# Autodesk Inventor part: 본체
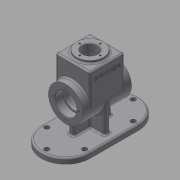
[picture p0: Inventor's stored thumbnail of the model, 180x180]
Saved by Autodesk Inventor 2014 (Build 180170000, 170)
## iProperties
Created: 2019-01
Part Number: 본체
Material: 일반
Document SubType Name: Modeling
Designer: mduedu
Density: 1 g/cm^3
Appearance: 기본값
Mass: 390.301 g
Surface Area: 916.19 cm^2
Volume: 390.301 cm^3
Author: mduedu
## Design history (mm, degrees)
sketch "스케치1"
  geometry: C1 r 32 at (0, 0); 1 further point
  constraints: 1 centre point, 1 coincident
  dimensions: "d0" = 64 diameter of C1
extrude "돌출1" new body sketch "스케치1" stored distance "d1" = 90; taper "d2" = 0 deg
sketch "스케치2"
  geometry: L1 (0, 32)-(60, 32); L2 (60, 32)-(60, -32); L3 (60, -32)-(0, -32); L4 (0, -32)-(0, 32); C1 r 32 at (0, 0) reference; 2 further points
  constraints: 8 end point, 2 parallel, 1 coincident, 1 horizontal, 1 midpoint, 1 perpendicular, 1 tangent
  dimensions: "d5" = 60 distance between parallel lines of L4 L2
extrude "돌출2" join sketch "스케치2" stored distance "d7" = 64; taper "d8" = 0 deg
sketch "스케치3"
  geometry: C1 r 25 at (32, 32); 1 further point
  constraints: 1 centre point, 1 coincident
  dimensions: "d9" = 50 diameter of C1
extrude "돌출3" join sketch "스케치3" distance "d10" = 5; taper "d11" = 0 deg
sketch "스케치4"
  geometry: L1 (50, 25)-(0, 25); L2 (0, 25)-(0, -25); L3 (0, -25)-(50, -25); L4 (50, -25)-(50, 25); L5 (65, -25)-(65, 25) reference; A1 r 25 centre (0, 0) between (0, 25) and (0, -25); A2 r 25 centre (0, 0) between (0, -25) and (0, 25); 2 further points
  constraints: 8 end point, 4 point on circle, 2 centre point, 2 coincident, 2 parallel, 1 horizontal, 1 midpoint, 1 perpendicular, 1 tangent
  dimensions: "d12" = 50 diameter of A1; "d13" = 15 distance between parallel lines of L4 L5
extrude "돌출4" cut sketch "스케치4" stored distance "d14" = 48; taper "d15" = 0 deg
sketch "스케치5"
  geometry: C1 r 20 at (0, 0); 1 further point
  constraints: 1 centre point, 1 coincident
  dimensions: "d16" = 40 diameter of C1
extrude "돌출5" cut sketch "스케치5" distance "d17" = 15; taper "d18" = 0 deg
sketch "스케치6"
  geometry: C1 r 17 at (0, 0); 1 further point
  constraints: 1 centre point, 1 coincident
  dimensions: "d19" = 34 diameter of C1
extrude "돌출6" cut sketch "스케치6" stored distance "d20" = 15; taper "d21" = 0 deg
fillet "모깎기1" dims "d22" = 0.3
fillet "모깎기2" dims "d23" = 3
fillet "모깎기3" dims "d24" = 3
fillet "모깎기4" dims "d25" = 3
fillet "모깎기5" dims "d26" = 3
fillet "모깎기6" dims "d27" = 3
sketch "스케치7"
  geometry: C1 r 14 at (0, 0); 1 further point
  constraints: 1 centre point, 1 coincident
  dimensions: "d28" = 28 diameter of C1
extrude "돌출7" cut sketch "스케치7" stored distance "d29" = 15; taper "d30" = 0 deg
chamfer "모따기1" distance "d31" = 1; stored, may be unused: second distance "d32" = 2, angle "d33" = 45 deg
chamfer "모따기2" distance "d34" = 1; stored, may be unused: second distance "d35" = 2, angle "d36" = 45 deg
node "작업 평면1"
sketch "스케치8"
  geometry: L1 (45, 45)-(-45, 45); L2 (-45, 45)-(-45, -45); L3 (-45, -45)-(45, -45); L4 (45, -45)-(45, 45); L5 (45, 45)-(-45, -45); L6 (-45, 45)-(45, -45); A1 r 45 centre (45, 0) between (45, -45) and (45, 45); A2 r 45 centre (-45, 0) between (-45, 45) and (-45, -45); A3 r 45 centre (45, 0) between (0, 0) and (45, -45); A4 r 45 centre (45, 0) between (0, 0) and (0, 0); A5 r 45 centre (45, 0) between (45, 45) and (0, 0); A6 r 45 centre (-45, 0) between (0, 0) and (-45, 45); A7 r 45 centre (-45, 0) between (-45, -45) and (0, 0); 1 further point
  constraints: 14 point on circle, 12 end point, 7 centre point, 7 midpoint, 2 parallel, 1 horizontal, 1 perpendicular
  dimensions: "d99" = 90 distance between parallel lines of L1 L3; "d101" = 90 distance between parallel lines of L2 L4
extrude "돌출8" join sketch "스케치8" distance "d41" = 10; taper "d42" = 0 deg
sketch "스케치9"
  geometry: L1 (-35, 5)-(35, 5); L2 (35, 5)-(35, -5); L3 (35, -5)-(-35, -5); L4 (-35, -5)-(-35, 5); 3 further points
  constraints: 8 end point, 2 midpoint, 2 parallel, 1 horizontal, 1 horizontal alignment, 1 perpendicular, 1 vertical alignment
  dimensions: "d52" = 10 distance of L1.end L2.end; "d54" = 70 distance of L1.start L1.end
extrude "돌출9" join sketch "스케치9" stored distance "d50" = 10; taper "d51" = 0 deg
sketch "스케치10"
  geometry: L1 (0, -25)-(47, -25) reference; L2 (50, -22)-(50, -14) reference; L3 (50, -14)-(64, -14) reference; L4 (64, -14)-(65, -15) reference; L5 (65, -15)-(65, -25) reference; L6 (65, -25)-(63, -25) reference; L7 (60, -28)-(60, -29) reference; L8 (57, -32)-(0, -32) reference; L9 (-31.607, -5)-(-55, -5) reference; L10 (-55, -5)-(-55, -45) reference; L11 (-65, -45)-(-65, 45) reference; L12 (-55, 45)-(-55, 5) reference; L13 (-55, 5)-(-31.607, 5) reference; L14 (0, 32)-(57, 32) reference; L15 (60, 29)-(60, 28) reference; L16 (63, 25)-(65, 25) reference; L17 (65, 25)-(65, 15) reference; L18 (65, 15)-(64, 14) reference; L19 (64, 14)-(50, 14) reference; L20 (50, 14)-(50, 22) reference; L21 (47, 25)-(0, 25) reference; L22 (-55, -45)-(-65, -45) reference; L23 (-65, 45)-(-55, 45) reference; L24 (0, 32)-(-55, 32); A1 r 25 centre (0, 0) between (0, 25) and (0, -25) reference; A2 r 3 centre (47, -22) between (47, -25) and (50, -22) reference; A3 r 3 centre (63, -28) between (63, -25) and (60, -28) reference; A4 r 3 centre (57, -29) between (57, -32) and (60, -29) reference; A5 r 32 centre (0, 0) between (-31.607, -5) and (0, -32) reference; A6 r 32 centre (0, 0) between (0, 32) and (-31.607, 5) reference; A7 r 3 centre (57, 29) between (60, 29) and (57, 32) reference; A8 r 3 centre (63, 28) between (60, 28) and (63, 25) reference; A9 r 3 centre (47, 22) between (50, 22) and (47, 25) reference
  constraints: 2 end point, 1 perpendicular, 1 point on line, 1 tangent
feature "리브1" sketch "스케치10" dims "d57" = 1, "d58" = 10, "d59" = 0, "d60" = 0, "d61" = 1, "d62" = 1
fillet "모깎기7" dims "d63" = 3
fillet "모깎기11" dims "d102" = 3
fillet "모깎기8" dims "d64" = 3
sketch "스케치11"
  geometry: L1 (8, -29)-(8, -8) reference; L2 (-8, -8)-(-8, -29) reference; L3 (-32, -8)-(-8, -8) reference; L4 (-38, 2)-(-38, -2) reference; L5 (-8, 8)-(-32, 8) reference; L6 (-8, 29)-(-8, 8) reference; L7 (8, 8)-(8, 29) reference; L8 (32, 8)-(8, 8) reference; L9 (38, -2)-(38, 2) reference; L10 (8, -8)-(32, -8) reference; L11 (-2, -35)-(2, -35) reference; L12 (2, 35)-(-2, 35) reference; L13 (-45, -45)-(45, -45) reference; L14 (45, 45)-(-45, 45) reference; L15 (-45, -35)-(45, -35); L16 (45, 35)-(-45, 35); A1 r 6 centre (-32, -2) between (-38, -2) and (-32, -8) reference; A2 r 6 centre (-32, 2) between (-32, 8) and (-38, 2) reference; A3 r 6 centre (32, 2) between (38, 2) and (32, 8) reference; A4 r 6 centre (32, -2) between (32, -8) and (38, -2) reference; A5 r 6 centre (2, -29) between (2, -35) and (8, -29) reference; A6 r 6 centre (-2, -29) between (-8, -29) and (-2, -35) reference; A7 r 6 centre (-2, 29) between (-2, 35) and (-8, 29) reference; A8 r 6 centre (2, 29) between (8, 29) and (2, 35) reference; A9 r 45 centre (-45, 0) between (-45, 45) and (-45, -45) reference; A10 r 45 centre (45, 0) between (45, -45) and (45, 45) reference; A11 r 35 centre (-45, 0) between (-45, 35) and (-45, -35); A12 r 35 centre (45, 0) between (45, -35) and (45, 35); 7 further points
  constraints: 6 point on circle, 4 coincident, 4 end point, 2 centre point, 3 other
  dimensions: "d103" = 10 distance between parallel lines of L16 L14
hole "구멍1" sketch "스케치11" at (-45, 35), (-80, 0), (-45, -35), (45, -35), (80, 0), (45, 35) diameter "d66" = 9; stored, may be unused: countersink angle "d70" = 90 deg, drill point angle "d72" = 118 deg; dims "d67" = 6, "d68" = 4, "d69" = 2, "d71" = 8
fillet "모깎기10" dims "d73" = 3
sketch "스케치12"
  geometry: L1 (-3, 57)-(-3, 19.596) reference; 2 further points
  constraints: 1 other
  dimensions: "d74" = 32 distance from line of point (29, 45) L1; "d75" = 45 distance of point (29, 45) point (29, 0)
feature "엠보싱1" sketch "스케치12" dims "d12" = 50, "d13" = 15, "d76" = 0.5, "d77" = 0
sketch "스케치13"
  geometry: 4 further points
  constraints: 4 other
hole "구멍2" sketch "스케치13" at (-25, 0), (0, -25), (25, 0), (0, 25) diameter "d78" = 3.242; stored, may be unused: countersink angle "d82" = 90 deg, drill point angle "d84" = 120 deg; dims "d79" = 7, "d80" = 4, "d81" = 2, "d83" = 9
sketch "스케치14"
  geometry: 4 further points
  constraints: 4 other
hole "구멍3" sketch "스케치14" at (-25, 0), (0, -25), (25, 0), (0, 25) diameter "d85" = 3.242; stored, may be unused: countersink angle "d89" = 90 deg, drill point angle "d91" = 120 deg; dims "d86" = 7, "d87" = 4, "d88" = 2, "d90" = 9
sketch "스케치15"
  geometry: 4 further points
  constraints: 4 other
hole "구멍4" sketch "스케치15" at (0, -19), (19, 0), (0, 19), (-19, 0) diameter "d92" = 3.242; stored, may be unused: countersink angle "d96" = 90 deg, drill point angle "d98" = 120 deg; dims "d93" = 8, "d94" = 4, "d95" = 2, "d97" = 10
node "솔리드1"
mirror "대칭1"
mirror "대칭2"
node "투영된 루프1"
node "투영된 루프2"
node "절단 모서리 투영1"
node "절단 모서리 투영2"
other parameters: "d37" = -65
